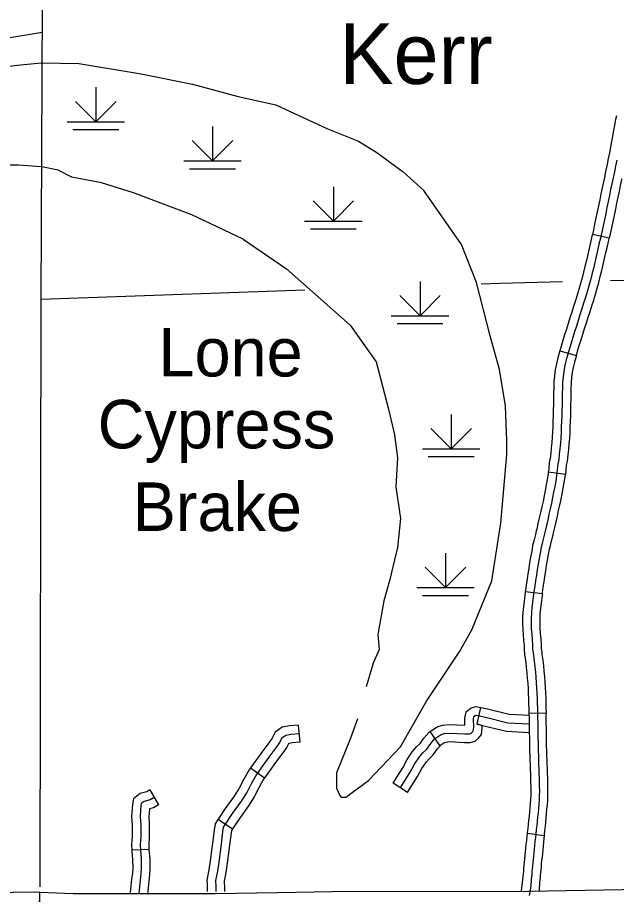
# Model space of a CAD drawing. Extents: x 1127717 to 1741049, y 2026793 to 2244711.
# Drawn here: x 1289221 to 1294439, y 2075216 to 2082851 of the extents above; entities that cross this region are included whole.
import ezdxf

# ---------------------------------------------------------------- set-up
doc = ezdxf.new("R2010")
doc.units = 0
for name, color, linetype in [('15', 7, 'Continuous'), ('2', 7, 'Continuous'), ('24', 7, 'Continuous'), ('31', 7, 'Continuous'), ('32', 7, 'Continuous'), ('35', 7, 'Continuous'), ('44', 7, 'Continuous'), ('47', 7, 'Continuous'), ('5', 7, 'Continuous')]:
    doc.layers.add(name, color=color, linetype=linetype)

msp = doc.modelspace()

# ---------------------------------------------------------------- linework, layer by layer
at = {"layer": '15'}
msp.add_line((1289414.5, 2074986.8), (1289413.8, 2075236.9), dxfattribs=at)
for points in [[(1291960.3, 2075242.5), (1293674.3, 2075245.9), (1294820.5, 2075264.7), (1298229, 2075302), (1299981.5, 2075316.3), (1302519.4, 2075326.7), (1304059.9, 2075347.2)], [(1289414.5, 2074986.8), (1289413.5, 2075103.2), (1289413.8, 2075236.9), (1289182.7, 2075233), (1288971, 2075227), (1288421.3, 2075214.2), (1287746.8, 2075197.1), (1287127, 2075181.2), (1286845.5, 2075174.1), (1286475.5, 2075164.7), (1286430.7, 2075163.7)], [(1289413.8, 2075236.9), (1289705.4, 2075225.3), (1290941.1, 2075223.3), (1291488.9, 2075232.9), (1291960.3, 2075242.5)]]:
    msp.add_lwpolyline(points, dxfattribs=at)
at = {"layer": '2'}
msp.add_lwpolyline([(1289442.4, 2084264.3), (1289424.8, 2080394.9), (1289413.9, 2075282.5)], dxfattribs=at)
at = {"layer": '31'}
for p, q in [((1294375.8, 2080929.6), (1294229.4, 2080962.4)), ((1293945.6, 2079950.4), (1294089.8, 2079909.1)), ((1293993.9, 2078871.6), (1293845.3, 2078891.5)), ((1293993.9, 2078871.6), (1293993.9, 2078871.6)), ((1293644.9, 2077855.1), (1293793.6, 2077835.9)), ((1293825.9, 2076795.3), (1293675.9, 2076791.4)), ((1293825.9, 2076795.2), (1293825.9, 2076795.3)), ((1293661.7, 2075748.6), (1293810.5, 2075729.6))]:
    msp.add_line(p, q, dxfattribs=at)
for points in [[(1294439.2, 2081996.3), (1294432, 2081962.1), (1294422.6, 2081914.7), (1294413.9, 2081867), (1294405.2, 2081819.4), (1294396.2, 2081771.3), (1294387.1, 2081722.4), (1294377.8, 2081673.1), (1294368.1, 2081623.4), (1294358.1, 2081573.1), (1294347.7, 2081522.3), (1294338.4, 2081478)], [(1294441.7, 2081608.9), (1294431.6, 2081558.2), (1294421.1, 2081507.1), (1294410.3, 2081455.7), (1294399.3, 2081404.3), (1294388.4, 2081352.9), (1294377.4, 2081301.3), (1294366.8, 2081249.3), (1294356, 2081196.6), (1294345.1, 2081143.6), (1294333.9, 2081090.2), (1294322.5, 2081036.8), (1294311, 2080983.3), (1294299, 2080929.9), (1294286.9, 2080876.7), (1294274.8, 2080823.7), (1294262.2, 2080770.9), (1294249.8, 2080718.5), (1294237.6, 2080666.6), (1294225.2, 2080615.3), (1294211.9, 2080564.5), (1294198.2, 2080514), (1294183.6, 2080463.6), (1294168.8, 2080413.4), (1294153, 2080363.4), (1294137.2, 2080313.7), (1294121.2, 2080264), (1294105.7, 2080214.4), (1294090.2, 2080164.9), (1294074.5, 2080115.7), (1294059.1, 2080066.5), (1294043.7, 2080017.4), (1294028.8, 2079968.5), (1294014.7, 2079919.3), (1294001.4, 2079870.3), (1293989.3, 2079821.4), (1293979.8, 2079772.5), (1293973.4, 2079723.4), (1293969.7, 2079674.1), (1293967.6, 2079625), (1293966.5, 2079576.4), (1293965.8, 2079528.1), (1293964.9, 2079480), (1293963.8, 2079431.9), (1293962.2, 2079384), (1293960.2, 2079336.2), (1293958.6, 2079288.4), (1293957, 2079240.5), (1293954, 2079192.7), (1293950.3, 2079145.3), (1293945.8, 2079098), (1293941.2, 2079050.8)], [(1294338.4, 2081478), (1294336.9, 2081471.2), (1294326, 2081419.9), (1294315.1, 2081368.5), (1294304, 2081316.7), (1294293.3, 2081264.3), (1294282.5, 2081211.7), (1294271.7, 2081158.8), (1294260.5, 2081105.8), (1294249.1, 2081052.5), (1294237.7, 2080999.3), (1294229.4, 2080962.4)], [(1294485.2, 2081447.2), (1294483.7, 2081440.1), (1294472.7, 2081388.7), (1294461.8, 2081337.3), (1294450.8, 2081286), (1294440.2, 2081234.2), (1294429.5, 2081181.6), (1294418.5, 2081128.3), (1294407.3, 2081074.6), (1294395.8, 2081021), (1294384.2, 2080967.2), (1294375.8, 2080929.6)], [(1294229.4, 2080962.4), (1294225.9, 2080946.4), (1294213.8, 2080893.4), (1294201.7, 2080840.8), (1294189.2, 2080788.3), (1294176.8, 2080735.7), (1294164.7, 2080684), (1294152.5, 2080633.6), (1294139.4, 2080583.8), (1294126, 2080534.2), (1294111.6, 2080484.7), (1294102.9, 2080455.1)], [(1294246.7, 2080412.6), (1294255.6, 2080442.5), (1294270.5, 2080493.7), (1294284.4, 2080545.2), (1294298, 2080596.9), (1294310.6, 2080649.2), (1294322.8, 2080701.3), (1294335.1, 2080753.6), (1294347.8, 2080806.6), (1294360, 2080860), (1294372.2, 2080913.4), (1294375.8, 2080929.6)], [(1294102.9, 2080455), (1294097, 2080435.3), (1294081.5, 2080386.1), (1294065.8, 2080336.5), (1294049.7, 2080286.7), (1294034.1, 2080236.7), (1294018.7, 2080187.5), (1294003, 2080138.3), (1293987.5, 2080088.9), (1293972.1, 2080039.5), (1293956.9, 2079989.8), (1293945.6, 2079950.4)], [(1294089.8, 2079909.1), (1294100.7, 2079947.2), (1294115.4, 2079995.2), (1294130.6, 2080044.1), (1294146, 2080093), (1294161.8, 2080142.3), (1294177.3, 2080192), (1294192.6, 2080241.3), (1294208.6, 2080290.8), (1294224.5, 2080340.8), (1294240.5, 2080391.5), (1294246.7, 2080412.6)], [(1293945.6, 2079950.4), (1293942.5, 2079939.5), (1293928.8, 2079889.1), (1293916, 2079837.5), (1293905.7, 2079784.5), (1293898.8, 2079731), (1293894.8, 2079678.6), (1293892.6, 2079627.5), (1293891.5, 2079577.8), (1293890.8, 2079529.3), (1293889.9, 2079481.5), (1293888.8, 2079434), (1293888, 2079409.4)], [(1294089.8, 2079909.1), (1294086.9, 2079899.2), (1294074, 2079851.4), (1294062.6, 2079805.2), (1294053.9, 2079760.5), (1294048.1, 2079715.8), (1294044.6, 2079669.6), (1294042.5, 2079622.6), (1294041.5, 2079575), (1294040.8, 2079526.8), (1294039.9, 2079478.4), (1294038.8, 2079429.8), (1294037.9, 2079404.6)], [(1293888, 2079409.4), (1293887.3, 2079386.8), (1293885.3, 2079339.1), (1293883.6, 2079290.9), (1293882, 2079244), (1293879.2, 2079198), (1293875.6, 2079151.7), (1293871.2, 2079105.3), (1293866.5, 2079057.8), (1293862.6, 2079015.1), (1293853, 2078977.4), (1293849.1, 2078920.2), (1293845.3, 2078891.5)], [(1294037.9, 2079404.6), (1294037.2, 2079381.2), (1294035.2, 2079333.4), (1294033.5, 2079285.9), (1294031.9, 2079236.9), (1294028.9, 2079187.5), (1294025, 2079138.8), (1294020.5, 2079090.8), (1294015.9, 2079043.8), (1294010.9, 2078989.5), (1294001.7, 2078953.5), (1293998.4, 2078905.1), (1293993.9, 2078871.6)], [(1293941.2, 2079050.8), (1293936.8, 2079002.3), (1293927.3, 2078965.5), (1293923.8, 2078912.7), (1293917.3, 2078864.1), (1293910.1, 2078815.4), (1293901.3, 2078767.4), (1293891.9, 2078719.3), (1293882.6, 2078671), (1293873, 2078622.7), (1293861.9, 2078574.9), (1293851, 2078526.3), (1293839.9, 2078477.7), (1293828.3, 2078429.3), (1293817.3, 2078380.5), (1293806.3, 2078331.7), (1293794.1, 2078284.9), (1293781.7, 2078238.1), (1293774.3, 2078188.8), (1293765, 2078140.6), (1293756.6, 2078092.6), (1293748.9, 2078044.6), (1293741.1, 2077996.8), (1293733.9, 2077949), (1293726.9, 2077901.4), (1293720.3, 2077853.7), (1293714.2, 2077806.2), (1293708.5, 2077759.1), (1293702.6, 2077713.2), (1293698.1, 2077667.2), (1293695.5, 2077621.1), (1293695.4, 2077574.8), (1293697.4, 2077528.3), (1293700.7, 2077481.9), (1293704.6, 2077435.4), (1293708.6, 2077388.4), (1293709, 2077350.7), (1293715.9, 2077298.8), (1293723.4, 2077246.5), (1293727.9, 2077198.5), (1293732.7, 2077152.2), (1293736.9, 2077105.6), (1293740.4, 2077059.4), (1293743.3, 2077013.8), (1293745.6, 2076968.6), (1293747.4, 2076924), (1293748.5, 2076879.8), (1293749.8, 2076836.1), (1293750.9, 2076792.9), (1293752.1, 2076750.3), (1293753, 2076708.1), (1293753.7, 2076666.2), (1293754.2, 2076624.6), (1293755.2, 2076582.9), (1293755.6, 2076543.9), (1293755.9, 2076505.4), (1293756.8, 2076466.6), (1293758.5, 2076427), (1293759.1, 2076387.5), (1293761.1, 2076347.3), (1293762.6, 2076308.4), (1293764.1, 2076270.1), (1293765.3, 2076231.6), (1293766.1, 2076193.1), (1293767, 2076155.2), (1293767.6, 2076117.1), (1293767.1, 2076078.6), (1293765, 2076040.5), (1293762.1, 2076002.7), (1293759, 2075965), (1293755.8, 2075927.6), (1293752.3, 2075890.3), (1293748.7, 2075853.5), (1293744.8, 2075816.8), (1293740.9, 2075780.8), (1293736.9, 2075745.4), (1293732.5, 2075710.9), (1293728.7, 2075676.6), (1293725, 2075643.6), (1293722, 2075611.3), (1293718.9, 2075579.9), (1293715.8, 2075549.3), (1293712.6, 2075519.5), (1293709.7, 2075490.5), (1293707.2, 2075462.5), (1293705, 2075436.2), (1293703, 2075411.8), (1293700.9, 2075389.2), (1293698.6, 2075368.3), (1293696.3, 2075348.1), (1293694.6, 2075328.4), (1293693.7, 2075309.1), (1293692.2, 2075290.1), (1293690.7, 2075271.7), (1293688.1, 2075254.6), (1293685, 2075238.2), (1293682.5, 2075221.5), (1293679.8, 2075206.3)], [(1293845.3, 2078891.5), (1293843, 2078874.6), (1293836.1, 2078827.7), (1293827.6, 2078781.3), (1293818.3, 2078733.6), (1293809, 2078685.4), (1293799.7, 2078638.5), (1293788.7, 2078591.5), (1293777.8, 2078542.8), (1293766.8, 2078494.8), (1293755.3, 2078446.2), (1293744.1, 2078397), (1293740.5, 2078381)], [(1293886.8, 2078348.1), (1293890.4, 2078364), (1293901.4, 2078412.3), (1293912.9, 2078460.7), (1293924.1, 2078509.7), (1293935, 2078558.2), (1293946.3, 2078606.9), (1293956.2, 2078656.6), (1293965.5, 2078705), (1293975, 2078753.5), (1293984.1, 2078803.2), (1293991.5, 2078853.6), (1293993.9, 2078871.6)], [(1293740.5, 2078381), (1293733.4, 2078349.4), (1293721.5, 2078304), (1293708.1, 2078253.3), (1293700.4, 2078201.5), (1293691.2, 2078154.1), (1293682.7, 2078105), (1293674.8, 2078056.6), (1293667, 2078008.3), (1293659.7, 2077960), (1293652.7, 2077912), (1293646, 2077863.6), (1293644.9, 2077855.1)], [(1293793.6, 2077835.9), (1293794.6, 2077843.8), (1293801.2, 2077890.7), (1293808.1, 2077938), (1293815.2, 2077985.2), (1293822.9, 2078032.6), (1293830.6, 2078080.2), (1293838.7, 2078127.1), (1293848.2, 2078176.1), (1293855.3, 2078222.9), (1293866.6, 2078265.8), (1293879.2, 2078314), (1293886.8, 2078348.1)], [(1293644.9, 2077855.1), (1293639.8, 2077815.5), (1293634.1, 2077768.3), (1293628.1, 2077721.6), (1293623.3, 2077673), (1293620.5, 2077623.3), (1293620.4, 2077573.3), (1293622.5, 2077524.1), (1293625.9, 2077476.1), (1293629.8, 2077429.1), (1293633.7, 2077384.8), (1293634.1, 2077345.3), (1293638.8, 2077309.7)], [(1293793.6, 2077835.9), (1293788.6, 2077796.9), (1293782.9, 2077749.9), (1293777.2, 2077704.7), (1293772.9, 2077661.4), (1293770.5, 2077618.9), (1293770.4, 2077576.3), (1293772.3, 2077532.6), (1293775.5, 2077487.7), (1293779.3, 2077441.7), (1293783.6, 2077392.1), (1293784, 2077356.1), (1293787.5, 2077329.5)], [(1293787.5, 2077329.5), (1293790.2, 2077309.1), (1293797.9, 2077255.4), (1293802.6, 2077205.8), (1293807.3, 2077159.4), (1293811.6, 2077111.8), (1293815.2, 2077064.7), (1293818.2, 2077018.1), (1293820.6, 2076972), (1293822.3, 2076926.4), (1293823.5, 2076881.9), (1293824.8, 2076838.2), (1293825.9, 2076795.3)], [(1293638.8, 2077309.7), (1293641.7, 2077288.5), (1293648.9, 2077237.7), (1293653.3, 2077191.2), (1293658, 2077145.1), (1293662.1, 2077099.4), (1293665.5, 2077054.2), (1293668.4, 2077009.4), (1293670.7, 2076965.3), (1293672.4, 2076921.6), (1293673.5, 2076877.7), (1293674.8, 2076834), (1293675.9, 2076791.4)], [(1293675.9, 2076791.5), (1293675.9, 2076791), (1293677.1, 2076748.4), (1293678, 2076706.6), (1293678.7, 2076665.1), (1293679.3, 2076623.3), (1293680.2, 2076581.7), (1293680.6, 2076543.2), (1293680.9, 2076504.3), (1293681.9, 2076464.1), (1293683.5, 2076424.8), (1293684.1, 2076385.1), (1293686.1, 2076344), (1293687.7, 2076305.5), (1293689.1, 2076267.5), (1293689.2, 2076263.2)], [(1293839.2, 2076267.9), (1293839, 2076272.7), (1293837.6, 2076311.3), (1293836, 2076350.7), (1293834.1, 2076389.9), (1293833.5, 2076429.1), (1293831.8, 2076469.1), (1293830.9, 2076506.6), (1293830.6, 2076544.6), (1293830.2, 2076584.2), (1293829.2, 2076625.9), (1293828.7, 2076667.3), (1293828, 2076709.5), (1293827, 2076752.1), (1293825.9, 2076794.9), (1293825.9, 2076795.2)], [(1293689.2, 2076263.2), (1293690.3, 2076229.7), (1293691.1, 2076191.4), (1293692, 2076153.8), (1293692.6, 2076117), (1293692.1, 2076081.1), (1293690.1, 2076045.4), (1293687.3, 2076008.6), (1293684.3, 2075971.3), (1293681.1, 2075934.4), (1293677.6, 2075897.4), (1293674.1, 2075861.1), (1293670.2, 2075824.9), (1293666.3, 2075789.1), (1293662.4, 2075754.4), (1293661.7, 2075748.6)], [(1293810.5, 2075729.6), (1293811.3, 2075736.5), (1293815.4, 2075772.5), (1293819.4, 2075808.8), (1293823.3, 2075845.9), (1293827, 2075883.2), (1293830.5, 2075920.9), (1293833.8, 2075958.7), (1293836.9, 2075996.8), (1293839.8, 2076035.6), (1293842, 2076076), (1293842.6, 2076117.1), (1293842, 2076156.7), (1293841.1, 2076194.8), (1293840.2, 2076233.6), (1293839.2, 2076267.9)], [(1293661.7, 2075748.6), (1293658, 2075719.7), (1293654.2, 2075684.9), (1293650.4, 2075651.4), (1293647.3, 2075618.5), (1293644.3, 2075587.3), (1293641.2, 2075557.1), (1293638, 2075527.2), (1293635.1, 2075497.6), (1293632.5, 2075469.1), (1293630.2, 2075442.4), (1293628.3, 2075418.3), (1293626.3, 2075396.8), (1293609.3, 2075244.8)], [(1293810.5, 2075729.6), (1293807, 2075702.1), (1293803.3, 2075668.3), (1293799.6, 2075635.9), (1293796.6, 2075604.2), (1293793.6, 2075572.5), (1293790.4, 2075541.4), (1293787.2, 2075511.8), (1293784.4, 2075483.4), (1293781.9, 2075456), (1293779.7, 2075430), (1293777.7, 2075405.4), (1293775.5, 2075381.6), (1293773.1, 2075360), (1293771, 2075340.8), (1293769.5, 2075323.3), (1293765.6, 2075247.4)]]:
    msp.add_lwpolyline(points, dxfattribs=at)
at = {"layer": '32'}
for p, q in [((1293224.8, 2076698.1), (1293256.6, 2076844.7)), ((1291667.1, 2076690.5), (1291679.9, 2076541)), ((1292901.5, 2076512.1), (1292815.1, 2076634.7)), ((1291251.4, 2076318.7), (1291373.3, 2076231.2)), ((1292618.1, 2076102.8), (1292492.4, 2076184.7)), ((1290374.8, 2076126.6), (1290449.8, 2075996.7)), ((1290968.5, 2075870.4), (1291093.7, 2075787.8)), ((1290215.7, 2075605.2), (1290365.7, 2075609.7))]:
    msp.add_line(p, q, dxfattribs=at)
for points in [[(1289435.4, 2082721.4), (1289330.4, 2082703.1), (1289081.9, 2082663.6)], [(1292815.1, 2076634.7), (1292852.8, 2076661.3), (1292882.3, 2076679.4), (1292925.2, 2076690.1), (1292981, 2076696.9), (1293119.4, 2076689.9), (1293117.1, 2076749.7), (1293130.4, 2076806.4), (1293171.9, 2076842), (1293216.9, 2076853.3), (1293256.6, 2076844.7)], [(1293256.6, 2076844.7), (1293316.4, 2076831.7), (1293503.1, 2076785.7), (1293682, 2076776.5)], [(1292555.3, 2076143.8), (1292574.1, 2076172.7), (1292641.9, 2076279.9), (1292679.9, 2076351.8), (1292723.3, 2076415.5), (1292751.8, 2076449.4), (1292785.7, 2076482), (1292820.9, 2076530.8), (1292857.5, 2076572.9), (1292894.1, 2076598.6), (1292911.7, 2076609.5), (1292938.9, 2076616.3), (1292983.6, 2076621.7), (1293117.8, 2076614.9), (1293155.8, 2076614.9), (1293170.7, 2076619), (1293182.9, 2076629.8), (1293191, 2076639.3), (1293195.1, 2076671.9), (1293192.4, 2076742.4), (1293197.8, 2076765.4), (1293207.3, 2076773.6), (1293218.2, 2076776.3), (1293299.5, 2076758.7), (1293492, 2076711.2), (1293678.1, 2076701.6)], [(1291667.1, 2076690.5), (1291592.4, 2076684.1), (1291527.9, 2076672.3), (1291465.1, 2076628), (1291438.4, 2076577.2), (1291411.4, 2076537.5), (1291348.9, 2076454.8), (1291297.5, 2076382.9), (1291251.4, 2076318.7)], [(1292492.4, 2076184.7), (1292511, 2076213.3), (1292577, 2076317.5), (1292615.5, 2076390.5), (1292663.4, 2076460.9), (1292696.9, 2076500.7), (1292728.8, 2076531.4), (1292762.1, 2076577.5), (1292806.9, 2076628.9), (1292815.1, 2076634.7)], [(1292901.5, 2076512.1), (1292935.4, 2076536), (1292941.2, 2076539.5), (1292952.5, 2076542.4), (1292986.2, 2076546.5), (1293115.9, 2076539.9), (1293165.8, 2076539.9), (1293207.4, 2076551.2), (1293236.5, 2076577.2), (1293262.7, 2076607.6), (1293270.3, 2076668.6), (1293269.5, 2076688.4), (1293224.8, 2076698.1)], [(1293224.8, 2076698.1), (1293282.6, 2076685.6), (1293481, 2076636.7), (1293674.2, 2076626.7)], [(1291673.5, 2076615.8), (1291602.4, 2076609.7), (1291557.7, 2076601.5), (1291523.1, 2076577.1), (1291502.8, 2076538.5), (1291472.3, 2076493.8), (1291409.3, 2076410.4), (1291358.5, 2076339.2), (1291301.6, 2076259.9), (1291256.9, 2076178.6), (1291218.3, 2076103.4), (1291170.6, 2076029.2), (1291092.2, 2075921.6), (1291013.7, 2075802.7), (1291007, 2075764.6), (1290993.6, 2075654.8), (1290973.4, 2075497.8), (1290962.2, 2075419.3), (1290946.5, 2075336.4), (1290948.7, 2075284.8), (1290948.7, 2075242.8)], [(1291679.9, 2076541), (1291612.3, 2076535.2), (1291587.4, 2076530.7), (1291581.1, 2076526.2), (1291567.2, 2076499.8), (1291533.2, 2076450), (1291469.7, 2076366), (1291419.5, 2076295.6), (1291373.3, 2076231.2)], [(1292618.1, 2076102.8), (1292637.3, 2076132.2), (1292706.9, 2076242.3), (1292744.3, 2076313), (1292783.2, 2076370.2), (1292806.6, 2076398.1), (1292842.5, 2076432.6), (1292879.7, 2076484.1), (1292908.1, 2076516.8), (1292901.5, 2076512.1)], [(1291251.4, 2076318.7), (1291238, 2076300), (1291190.6, 2076213.8), (1291153.2, 2076140.9), (1291108.7, 2076071.6), (1291030.6, 2075964.4), (1290968.5, 2075870.4)], [(1291373.3, 2076231.2), (1291365.1, 2076219.9), (1291323.1, 2076143.4), (1291283.3, 2076065.9), (1291232.6, 2075986.8), (1291153.8, 2075878.8), (1291093.7, 2075787.8)], [(1290374.8, 2076126.6), (1290346.6, 2076110.3), (1290289.5, 2076094.9), (1290230.2, 2076049.6), (1290222, 2076000), (1290214.3, 2075895.7), (1290218.7, 2075818.1), (1290218.7, 2075790.5), (1290218.7, 2075720.8), (1290214.4, 2075650.5), (1290215.7, 2075605.2)], [(1290412.3, 2076061.7), (1290375.6, 2076040.5), (1290323.3, 2076026.4), (1290299.4, 2076008), (1290296.5, 2075991), (1290289.5, 2075895), (1290293.7, 2075820.2), (1290293.7, 2075790.5), (1290293.7, 2075718.5), (1290289.5, 2075649.3), (1290290.9, 2075601.3), (1290297.9, 2075525), (1290299.4, 2075444.5), (1290296.5, 2075395.1), (1290289.5, 2075341.4), (1290277.5, 2075224.4)], [(1290449.8, 2075996.7), (1290404.6, 2075970.6), (1290369.5, 2075961.1), (1290364.6, 2075894.4), (1290368.7, 2075822.3), (1290368.7, 2075790.5), (1290368.7, 2075716.2), (1290364.5, 2075648.1), (1290365.7, 2075609.7)], [(1290968.5, 2075870.4), (1290942.6, 2075831.1), (1290932.8, 2075775.7), (1290919.1, 2075664.1), (1290899.1, 2075507.9), (1290888.2, 2075431.6), (1290871.2, 2075341.8), (1290872.7, 2075308)], [(1291093.7, 2075787.8), (1291084.9, 2075774.4), (1291081.2, 2075753.6), (1291068, 2075645.4), (1291047.7, 2075487.7), (1291036.2, 2075407), (1291021.8, 2075330.9), (1291022.5, 2075314.5)], [(1290215.7, 2075605.3), (1290216, 2075596.7), (1290223, 2075520.9), (1290224.3, 2075446), (1290221.8, 2075402.2), (1290215, 2075350.1), (1290202.9, 2075232)], [(1290365.7, 2075609.7), (1290365.8, 2075605.8), (1290372.9, 2075529.2), (1290374.4, 2075443.1), (1290371.2, 2075388.1), (1290364, 2075332.8), (1290352.1, 2075216.8)], [(1290872.7, 2075308), (1290873.7, 2075283.2), (1290873.7, 2075242.9)], [(1291022.5, 2075314.5), (1291023.7, 2075286.4), (1291023.7, 2075242.6)]]:
    msp.add_lwpolyline(points, dxfattribs=at)
at = {"layer": '44'}
for p, q in [((1289903.6, 2082244.4), (1289903.6, 2081944.4)), ((1289903.6, 2081944.4), (1289726.8, 2082121.2)), ((1289903.6, 2081944.4), (1290080.4, 2082121.2)), ((1289653.6, 2081944.4), (1290153.6, 2081944.4)), ((1290919.2, 2081903), (1290919.2, 2081603)), ((1289703.6, 2081876.3), (1290103.6, 2081876.3)), ((1290919.2, 2081603), (1290742.4, 2081779.8)), ((1290919.2, 2081603), (1291095.9, 2081779.8)), ((1290669.2, 2081603), (1291169.2, 2081603)), ((1290719.2, 2081534.9), (1291119.2, 2081534.9)), ((1291972.3, 2081378.5), (1291972.3, 2081078.5)), ((1291972.3, 2081078.5), (1291795.6, 2081255.3)), ((1291972.3, 2081078.5), (1292149.1, 2081255.3)), ((1291722.3, 2081078.5), (1292222.3, 2081078.5)), ((1291772.3, 2081010.4), (1292172.3, 2081010.4)), ((1292727.4, 2080554.2), (1292727.4, 2080254.2)), ((1292727.4, 2080254.2), (1292550.6, 2080431)), ((1292727.4, 2080254.2), (1292904.1, 2080431)), ((1292477.4, 2080254.2), (1292977.4, 2080254.2)), ((1292527.4, 2080186.1), (1292927.4, 2080186.1)), ((1292998.3, 2079396.1), (1292998.3, 2079096.1)), ((1292998.3, 2079096.1), (1292821.5, 2079272.9)), ((1292998.3, 2079096.1), (1293175.1, 2079272.9)), ((1292748.3, 2079096.1), (1293248.3, 2079096.1)), ((1292798.3, 2079027.9), (1293198.3, 2079027.9)), ((1292949, 2078188.7), (1292949, 2077888.7)), ((1292949, 2077888.7), (1292772.3, 2078065.4)), ((1292949, 2077888.7), (1293125.8, 2078065.4)), ((1292699, 2077888.7), (1293199, 2077888.7)), ((1292749, 2077820.5), (1293149, 2077820.5))]:
    msp.add_line(p, q, dxfattribs=at)
at = {"layer": '47'}
for points in [[(1289072.9, 2082418.3), (1289248.1, 2082439.4), (1289427.7, 2082455.5), (1289434.2, 2082455.9)], [(1289431, 2082455.7), (1289755.3, 2082451.4), (1290298.1, 2082359.7), (1290745.4, 2082271.7), (1291142.9, 2082164.6), (1291471.7, 2082092), (1291915.1, 2081885.5)], [(1291915.1, 2081885.5), (1292190.4, 2081774.6), (1292350.9, 2081675.1), (1292580.3, 2081506.9), (1292761.2, 2081344.3)], [(1289430, 2081552.5), (1289228.5, 2081565.3), (1289103.9, 2081566.4)], [(1291188, 2080922.7), (1290740.7, 2081133), (1290492.2, 2081224.8), (1290232.3, 2081324.2), (1289953.2, 2081412.2), (1289693.3, 2081461.9), (1289574.4, 2081522.2), (1289433, 2081551.3)], [(1292183.5, 2076745.9), (1292120.3, 2076567), (1292001.1, 2076275.4), (1292001.1, 2076209.1), (1292001.1, 2076142.9), (1292027.6, 2076076.6), (1292040.9, 2076063.3), (1292080.6, 2076063.3), (1292279.3, 2076209.1), (1292557.6, 2076500.7), (1292782.8, 2076898.4), (1293074.3, 2077335.8), (1293180.3, 2077521.3), (1293352.5, 2077945.5), (1293432, 2078449.2), (1293485, 2079045.6), (1293485, 2079164.9), (1293471.8, 2079469.8), (1293418.8, 2079787.9), (1293339.3, 2080079.5), (1293220, 2080543.4), (1293087.6, 2080874.7), (1292761.2, 2081344.3)], [(1291188, 2080922.7), (1291563.9, 2080662), (1292120.3, 2080171.6), (1292345.6, 2079853.5), (1292451.6, 2079442.6), (1292504.6, 2079217.2), (1292531.1, 2079018.4), (1292517.8, 2078766.6), (1292557.6, 2078488.2), (1292531.1, 2078236.4), (1292504.6, 2078130.4), (1292464.8, 2077958.1), (1292411.8, 2077772.5), (1292358.8, 2077480.9), (1292372.1, 2077348.3), (1292319.1, 2077229), (1292258.7, 2077023.5)]]:
    msp.add_lwpolyline(points, dxfattribs=at)
at = {"layer": '5'}
for points in [[(1293970.3, 2080549.9), (1293425, 2080536.8), (1293260.6, 2080531)], [(1294741.1, 2080568.5), (1294387.6, 2080560)], [(1291724.1, 2080476.5), (1289424.8, 2080394.9)]]:
    msp.add_lwpolyline(points, dxfattribs=at)

# ---------------------------------------------------------------- texts
at = {"layer": '24'}
msp.add_text('Kerr', height=528, dxfattribs=at).set_placement((1292026, 2082272.8))
at = {"layer": '35'}
for s, p in [('Lone', (1290449, 2079726.1)), ('Cypress', (1289918.7, 2079100.1)), ('Brake', (1290223.2, 2078381))]:
    msp.add_text(s, height=422.4, dxfattribs=at).set_placement(p)

doc.saveas('drawing.dxf')
